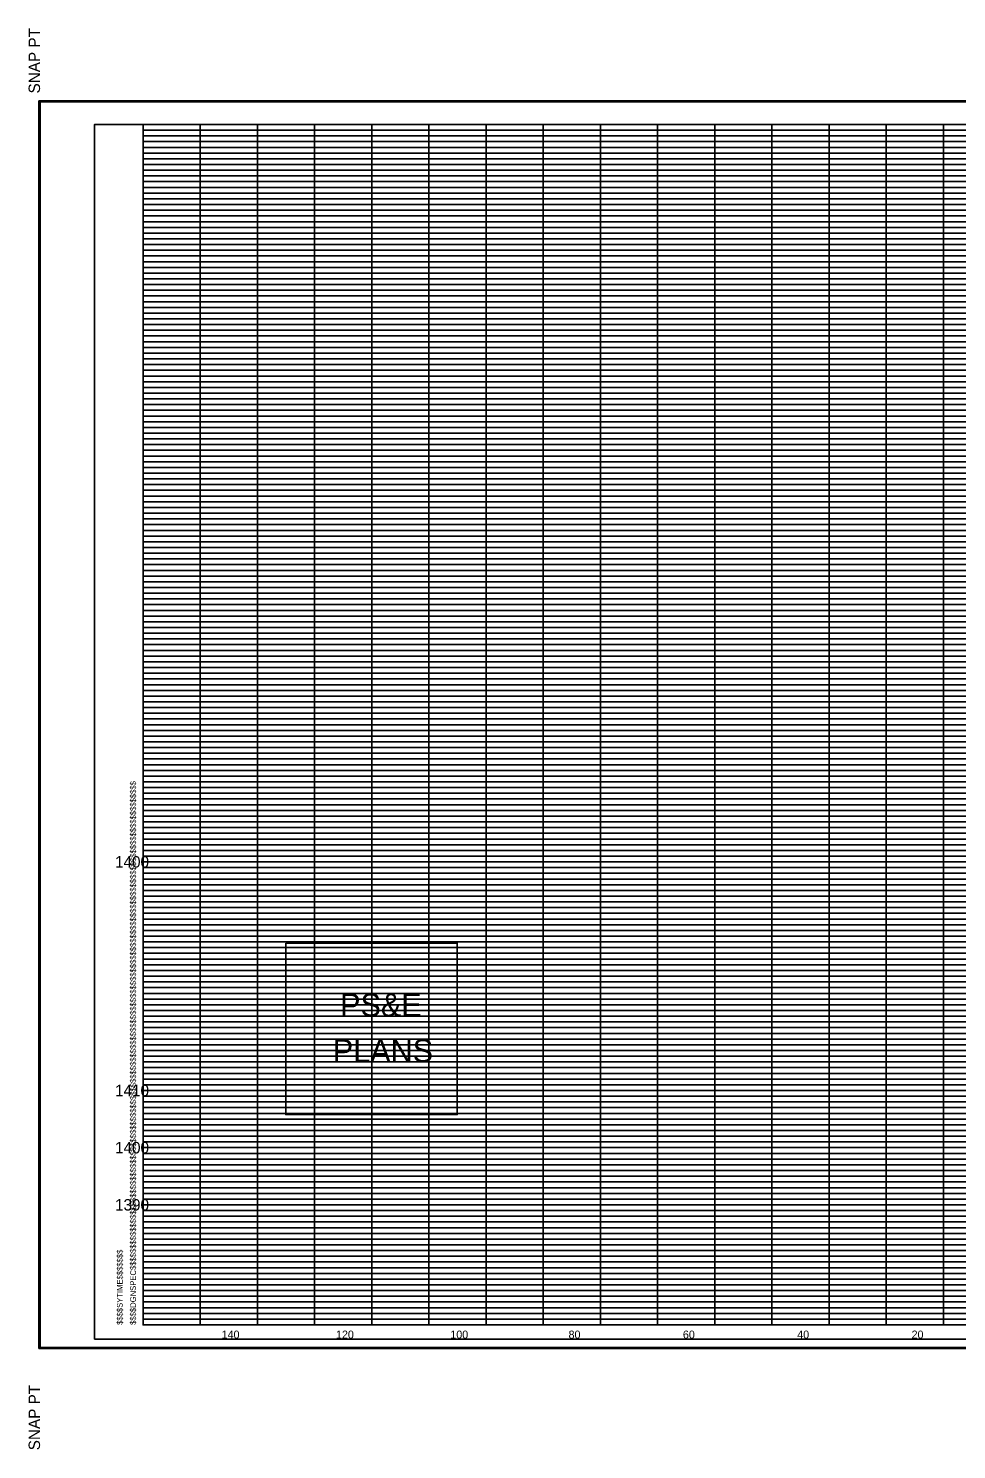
# Model space of a CAD drawing. Extents: x 980 to 1324, y 978 to 1497.
# Drawn here: x 979.9 to 1142.3, y 1248.2 to 1496.8 of the extents above; entities that cross this region are included whole.
import ezdxf

# ---------------------------------------------------------------- set-up
doc = ezdxf.new("R2010")
doc.units = 0
for name, color, linetype in [('DESIGN - SHEET - Corner Text', 7, 'Continuous'), ('DESIGN - SHEET - Light Grid', 7, 'Continuous'), ('DESIGN - SHEET - Linework', 7, 'Continuous'), ('DESIGN - SHEET - Plot Shape', 7, 'Continuous'), ('DESIGN - TYPICAL - Text', 7, 'Continuous')]:
    doc.layers.add(name, color=color, linetype=linetype)

# ---------------------------------------------------------------- blocks, each defined once
blk = doc.blocks.new('XSTSHT')
at = {"layer": 'DESIGN - SHEET - Light Grid'}
for p, q in [((0, 20.9), (8, 20.9)), ((8, 20.9), (16, 20.9)), ((0, 20.8), (8, 20.8)), ((0, 20.7), (8, 20.7)), ((8, 20.8), (16, 20.8)), ((8, 20.7), (16, 20.7)), ((0, 20.6), (8, 20.6)), ((0, 20.5), (8, 20.5)), ((0, 20.4), (8, 20.4)), ((8, 20.6), (16, 20.6)), ((8, 20.5), (16, 20.5)), ((8, 20.4), (16, 20.4)), ((0, 20.3), (8, 20.3)), ((0, 20.2), (8, 20.2)), ((8, 20.3), (16, 20.3)), ((8, 20.2), (16, 20.2)), ((0, 20.1), (8, 20.1)), ((0, 19.9), (8, 19.9)), ((8, 20.1), (16, 20.1)), ((8, 19.9), (16, 19.9)), ((0, 19.8), (8, 19.8)), ((0, 19.7), (8, 19.7)), ((8, 19.8), (16, 19.8)), ((8, 19.7), (16, 19.7)), ((0, 19.6), (8, 19.6)), ((0, 19.5), (8, 19.5)), ((0, 19.4), (8, 19.4)), ((8, 19.6), (16, 19.6)), ((8, 19.5), (16, 19.5)), ((8, 19.4), (16, 19.4)), ((0, 19.3), (8, 19.3)), ((0, 19.2), (8, 19.2)), ((8, 19.3), (16, 19.3)), ((8, 19.2), (16, 19.2)), ((0, 19.1), (8, 19.1)), ((0, 18.9), (8, 18.9)), ((8, 19.1), (16, 19.1)), ((8, 18.9), (16, 18.9)), ((0, 18.8), (8, 18.8)), ((0, 18.7), (8, 18.7)), ((8, 18.8), (16, 18.8)), ((8, 18.7), (16, 18.7)), ((0, 18.6), (8, 18.6)), ((0, 18.5), (8, 18.5)), ((0, 18.4), (8, 18.4)), ((8, 18.6), (16, 18.6)), ((8, 18.5), (16, 18.5)), ((8, 18.4), (16, 18.4)), ((0, 18.3), (8, 18.3)), ((0, 18.2), (8, 18.2)), ((8, 18.3), (16, 18.3)), ((8, 18.2), (16, 18.2)), ((0, 18.1), (8, 18.1)), ((8, 18.1), (16, 18.1)), ((0, 17.9), (8, 17.9)), ((0, 17.8), (8, 17.8)), ((0, 17.7), (8, 17.7)), ((8, 17.9), (16, 17.9)), ((8, 17.8), (16, 17.8)), ((8, 17.7), (16, 17.7)), ((0, 17.6), (8, 17.6)), ((0, 17.5), (8, 17.5)), ((8, 17.6), (16, 17.6)), ((8, 17.5), (16, 17.5)), ((0, 17.4), (8, 17.4)), ((0, 17.3), (8, 17.3)), ((0, 17.2), (8, 17.2)), ((8, 17.4), (16, 17.4)), ((8, 17.3), (16, 17.3)), ((8, 17.2), (16, 17.2)), ((0, 17.1), (8, 17.1)), ((8, 17.1), (16, 17.1)), ((0, 16.9), (8, 16.9)), ((0, 16.8), (8, 16.8)), ((0, 16.7), (8, 16.7)), ((8, 16.9), (16, 16.9)), ((8, 16.8), (16, 16.8)), ((8, 16.7), (16, 16.7)), ((0, 16.6), (8, 16.6)), ((0, 16.5), (8, 16.5)), ((8, 16.6), (16, 16.6)), ((8, 16.5), (16, 16.5)), ((0, 16.4), (8, 16.4)), ((0, 16.3), (8, 16.3)), ((0, 16.2), (8, 16.2)), ((8, 16.4), (16, 16.4)), ((8, 16.3), (16, 16.3)), ((8, 16.2), (16, 16.2)), ((0, 16.1), (8, 16.1)), ((8, 16.1), (16, 16.1)), ((0, 15.9), (8, 15.9)), ((0, 15.8), (8, 15.8)), ((0, 15.7), (8, 15.7)), ((8, 15.9), (16, 15.9)), ((8, 15.8), (16, 15.8)), ((8, 15.7), (16, 15.7)), ((0, 15.6), (8, 15.6)), ((0, 15.5), (8, 15.5)), ((8, 15.6), (16, 15.6)), ((8, 15.5), (16, 15.5)), ((0, 15.4), (8, 15.4)), ((0, 15.3), (8, 15.3)), ((0, 15.2), (8, 15.2)), ((8, 15.4), (16, 15.4)), ((8, 15.3), (16, 15.3)), ((8, 15.2), (16, 15.2)), ((0, 15.1), (8, 15.1)), ((8, 15.1), (16, 15.1)), ((0, 14.9), (8, 14.9)), ((0, 14.8), (8, 14.8)), ((0, 14.7), (8, 14.7)), ((8, 14.9), (16, 14.9)), ((8, 14.8), (16, 14.8)), ((8, 14.7), (16, 14.7)), ((0, 14.6), (8, 14.6)), ((0, 14.5), (8, 14.5)), ((8, 14.6), (16, 14.6)), ((8, 14.5), (16, 14.5)), ((0, 14.4), (8, 14.4)), ((0, 14.3), (8, 14.3)), ((0, 14.2), (8, 14.2)), ((8, 14.4), (16, 14.4)), ((8, 14.3), (16, 14.3)), ((8, 14.2), (16, 14.2)), ((0, 14.1), (8, 14.1)), ((8, 14.1), (16, 14.1)), ((0, 13.9), (8, 13.9)), ((0, 13.8), (8, 13.8)), ((0, 13.7), (8, 13.7)), ((8, 13.9), (16, 13.9)), ((8, 13.8), (16, 13.8)), ((8, 13.7), (16, 13.7)), ((0, 13.6), (8, 13.6)), ((0, 13.5), (8, 13.5)), ((8, 13.6), (16, 13.6)), ((8, 13.5), (16, 13.5)), ((0, 13.4), (8, 13.4)), ((0, 13.3), (8, 13.3)), ((0, 13.2), (8, 13.2)), ((8, 13.4), (16, 13.4)), ((8, 13.3), (16, 13.3)), ((8, 13.2), (16, 13.2)), ((0, 13.1), (8, 13.1)), ((8, 13.1), (16, 13.1)), ((0, 12.9), (8, 12.9)), ((0, 12.8), (8, 12.8)), ((0, 12.7), (8, 12.7)), ((8, 12.9), (16, 12.9)), ((8, 12.8), (16, 12.8)), ((8, 12.7), (16, 12.7)), ((0, 12.6), (8, 12.6)), ((0, 12.5), (8, 12.5)), ((8, 12.6), (16, 12.6)), ((8, 12.5), (16, 12.5)), ((0, 12.4), (8, 12.4)), ((0, 12.3), (8, 12.3)), ((0, 12.2), (8, 12.2)), ((8, 12.4), (16, 12.4)), ((8, 12.3), (16, 12.3)), ((8, 12.2), (16, 12.2)), ((0, 12.1), (8, 12.1)), ((8, 12.1), (16, 12.1)), ((0, 11.9), (8, 11.9)), ((0, 11.8), (8, 11.8)), ((0, 11.7), (8, 11.7)), ((8, 11.9), (16, 11.9)), ((8, 11.8), (16, 11.8)), ((8, 11.7), (16, 11.7)), ((0, 11.6), (8, 11.6)), ((0, 11.5), (8, 11.5)), ((8, 11.6), (16, 11.6)), ((8, 11.5), (16, 11.5)), ((0, 11.4), (8, 11.4)), ((0, 11.3), (8, 11.3)), ((0, 11.2), (8, 11.2)), ((8, 11.4), (16, 11.4)), ((8, 11.3), (16, 11.3)), ((8, 11.2), (16, 11.2)), ((0, 11.1), (8, 11.1)), ((8, 11.1), (16, 11.1)), ((0, 10.9), (8, 10.9)), ((0, 10.8), (8, 10.8)), ((0, 10.7), (8, 10.7)), ((8, 10.9), (16, 10.9)), ((8, 10.8), (16, 10.8)), ((8, 10.7), (16, 10.7)), ((0, 10.6), (8, 10.6)), ((0, 10.5), (8, 10.5)), ((8, 10.6), (16, 10.6)), ((8, 10.5), (16, 10.5)), ((0, 10.4), (8, 10.4)), ((0, 10.3), (8, 10.3)), ((0, 10.2), (8, 10.2)), ((8, 10.4), (16, 10.4)), ((8, 10.3), (16, 10.3)), ((8, 10.2), (16, 10.2)), ((0, 10.1), (8, 10.1)), ((8, 10.1), (16, 10.1)), ((0, 9.9), (8, 9.9)), ((0, 9.8), (8, 9.8)), ((0, 9.7), (8, 9.7)), ((8, 9.9), (16, 9.9)), ((8, 9.8), (16, 9.8)), ((8, 9.7), (16, 9.7)), ((0, 9.6), (8, 9.6)), ((0, 9.5), (8, 9.5)), ((8, 9.6), (16, 9.6)), ((8, 9.5), (16, 9.5)), ((0, 9.4), (8, 9.4)), ((0, 9.3), (8, 9.3)), ((0, 9.2), (8, 9.2)), ((8, 9.4), (16, 9.4)), ((8, 9.3), (16, 9.3)), ((8, 9.2), (16, 9.2)), ((0, 9.1), (8, 9.1)), ((8, 9.1), (16, 9.1)), ((0, 8.9), (8, 8.9)), ((0, 8.8), (8, 8.8)), ((8, 8.9), (16, 8.9)), ((8, 8.8), (16, 8.8)), ((0, 8.7), (8, 8.7)), ((0, 8.6), (8, 8.6)), ((0, 8.5), (8, 8.5)), ((8, 8.7), (16, 8.7)), ((8, 8.6), (16, 8.6)), ((8, 8.5), (16, 8.5)), ((0, 8.4), (8, 8.4)), ((0, 8.3), (8, 8.3)), ((8, 8.4), (16, 8.4)), ((8, 8.3), (16, 8.3)), ((0, 8.2), (8, 8.2)), ((0, 8.1), (8, 8.1)), ((8, 8.2), (16, 8.2)), ((8, 8.1), (16, 8.1)), ((0, 7.9), (8, 7.9)), ((0, 7.8), (8, 7.8)), ((8, 7.9), (16, 7.9)), ((8, 7.8), (16, 7.8)), ((0, 7.7), (8, 7.7)), ((0, 7.6), (8, 7.6)), ((0, 7.5), (8, 7.5)), ((8, 7.7), (16, 7.7)), ((8, 7.6), (16, 7.6)), ((8, 7.5), (16, 7.5)), ((0, 7.4), (8, 7.4)), ((0, 7.3), (8, 7.3)), ((8, 7.4), (16, 7.4)), ((8, 7.3), (16, 7.3)), ((0, 7.2), (8, 7.2)), ((0, 7.1), (8, 7.1)), ((8, 7.2), (16, 7.2)), ((8, 7.1), (16, 7.1)), ((0, 6.9), (8, 6.9)), ((0, 6.8), (8, 6.8)), ((8, 6.9), (16, 6.9)), ((8, 6.8), (16, 6.8)), ((0, 6.7), (8, 6.7)), ((0, 6.6), (8, 6.6)), ((0, 6.5), (8, 6.5)), ((8, 6.7), (16, 6.7)), ((8, 6.6), (16, 6.6)), ((8, 6.5), (16, 6.5)), ((0, 6.4), (8, 6.4)), ((0, 6.3), (8, 6.3)), ((8, 6.4), (16, 6.4)), ((8, 6.3), (16, 6.3)), ((0, 6.2), (8, 6.2)), ((0, 6.1), (8, 6.1)), ((8, 6.2), (16, 6.2)), ((8, 6.1), (16, 6.1)), ((0, 5.9), (8, 5.9)), ((0, 5.8), (8, 5.8)), ((8, 5.9), (16, 5.9)), ((8, 5.8), (16, 5.8)), ((0, 5.7), (8, 5.7)), ((0, 5.6), (8, 5.6)), ((0, 5.5), (8, 5.5)), ((8, 5.7), (16, 5.7)), ((8, 5.6), (16, 5.6)), ((8, 5.5), (16, 5.5)), ((0, 5.4), (8, 5.4)), ((0, 5.3), (8, 5.3)), ((8, 5.4), (16, 5.4)), ((8, 5.3), (16, 5.3)), ((0, 5.2), (8, 5.2)), ((0, 5.1), (8, 5.1)), ((8, 5.2), (16, 5.2)), ((8, 5.1), (16, 5.1)), ((0, 4.9), (8, 4.9)), ((0, 4.8), (8, 4.8)), ((8, 4.9), (16, 4.9)), ((8, 4.8), (16, 4.8)), ((0, 4.7), (8, 4.7)), ((0, 4.6), (8, 4.6)), ((0, 4.5), (8, 4.5)), ((8, 4.7), (16, 4.7)), ((8, 4.6), (16, 4.6)), ((8, 4.5), (16, 4.5)), ((0, 4.4), (8, 4.4)), ((0, 4.3), (8, 4.3)), ((8, 4.4), (16, 4.4)), ((8, 4.3), (16, 4.3)), ((0, 4.2), (8, 4.2)), ((0, 4.1), (8, 4.1)), ((8, 4.2), (16, 4.2)), ((8, 4.1), (16, 4.1)), ((0, 3.9), (8, 3.9)), ((0, 3.8), (8, 3.8)), ((8, 3.9), (16, 3.9)), ((8, 3.8), (16, 3.8)), ((0, 3.7), (8, 3.7)), ((0, 3.6), (8, 3.6)), ((0, 3.5), (8, 3.5)), ((8, 3.7), (16, 3.7)), ((8, 3.6), (16, 3.6)), ((8, 3.5), (16, 3.5)), ((0, 3.4), (8, 3.4)), ((0, 3.3), (8, 3.3)), ((8, 3.4), (16, 3.4)), ((8, 3.3), (16, 3.3)), ((0, 3.2), (8, 3.2)), ((0, 3.1), (8, 3.1)), ((8, 3.2), (16, 3.2)), ((8, 3.1), (16, 3.1)), ((0, 2.9), (8, 2.9)), ((0, 2.8), (8, 2.8)), ((8, 2.9), (16, 2.9)), ((8, 2.8), (16, 2.8)), ((0, 2.7), (8, 2.7)), ((0, 2.6), (8, 2.6)), ((0, 2.5), (8, 2.5)), ((8, 2.7), (16, 2.7)), ((8, 2.6), (16, 2.6)), ((8, 2.5), (16, 2.5)), ((0, 2.4), (8, 2.4)), ((0, 2.3), (8, 2.3)), ((8, 2.4), (16, 2.4)), ((8, 2.3), (16, 2.3)), ((0, 2.2), (8, 2.2)), ((0, 2.1), (8, 2.1)), ((8, 2.2), (16, 2.2)), ((8, 2.1), (16, 2.1)), ((0, 1.9), (8, 1.9)), ((0, 1.8), (8, 1.8)), ((8, 1.9), (16, 1.9)), ((8, 1.8), (16, 1.8)), ((0, 1.7), (8, 1.7)), ((0, 1.6), (8, 1.6)), ((0, 1.5), (8, 1.5)), ((8, 1.7), (16, 1.7)), ((8, 1.6), (16, 1.6)), ((8, 1.5), (16, 1.5)), ((0, 1.4), (8, 1.4)), ((0, 1.3), (8, 1.3)), ((8, 1.4), (16, 1.4)), ((8, 1.3), (16, 1.3)), ((0, 1.2), (8, 1.2)), ((0, 1.1), (8, 1.1)), ((8, 1.2), (16, 1.2)), ((8, 1.1), (16, 1.1)), ((0, 0.9), (8, 0.9)), ((0, 0.8), (8, 0.8)), ((8, 0.9), (16, 0.9)), ((8, 0.8), (16, 0.8)), ((0, 0.7), (8, 0.7)), ((0, 0.6), (8, 0.6)), ((0, 0.5), (8, 0.5)), ((8, 0.7), (16, 0.7)), ((8, 0.6), (16, 0.6)), ((8, 0.5), (16, 0.5)), ((0, 0.4), (8, 0.4)), ((0, 0.3), (8, 0.3)), ((8, 0.4), (16, 0.4)), ((8, 0.3), (16, 0.3)), ((0, 0.2), (8, 0.2)), ((0, 0.1), (8, 0.1)), ((8, 0.2), (16, 0.2)), ((8, 0.1), (16, 0.1))]:
    blk.add_line(p, q, dxfattribs=at)
at = {"layer": 'DESIGN - SHEET - Linework'}
for p, q in [((-1.823, -0.414), (-1.823, 21.414)), ((-1.823, 21.414), (32.217, 21.414)), ((1, 0), (1, 21)), ((2, 0), (2, 21)), ((3, 0), (3, 21)), ((4, 0), (4, 21)), ((5, 0), (5, 21)), ((6, 0), (6, 21)), ((7, 0), (7, 21)), ((8, 0), (8, 21)), ((9, 0), (9, 21)), ((10, 0), (10, 21)), ((11, 0), (11, 21)), ((12, 0), (12, 21)), ((13, 0), (13, 21)), ((14, 0), (14, 21)), ((0, 20), (28, 20)), ((0, 19), (32, 19)), ((0, 18), (32, 18)), ((0, 17), (32, 17)), ((0, 16), (32, 16)), ((0, 15), (32, 15)), ((0, 14), (32, 14)), ((0, 13), (32, 13)), ((0, 12), (32, 12)), ((0, 11), (32, 11)), ((0, 10), (32, 10)), ((0, 9), (32, 9)), ((0, 8), (32, 8)), ((0, 7), (32, 7)), ((0, 6), (32, 6)), ((0, 5), (32, 5)), ((0, 4), (32, 4)), ((0, 3), (32, 3)), ((0, 2), (32, 2)), ((0, 1), (32, 1)), ((-1.823, -0.414), (32.217, -0.414))]:
    blk.add_line(p, q, dxfattribs=at)
blk.add_lwpolyline([(0, 21), (0, 0), (32, 0), (32, 21), (0, 21)], dxfattribs=at)
at = {"layer": 'DESIGN - SHEET - Plot Shape'}
for points in [[(-1.803, 21.394), (32.197, 21.394), (32.197, -0.394), (-1.803, -0.394)], [(-0.85, 21), (32, 21), (32, -0.25), (-0.85, -0.25)]]:
    blk.add_lwpolyline(points, close=True, dxfattribs=at)
at = {"layer": 'DESIGN - SHEET - Corner Text'}
for s, height, p in [('  SNAP PT', 0.2, (-1.803, 21.394)), ('$$$$DGNSPEC$$$$$$$$$$$$$$$$$$$$$$$$$$$$$$$$$$$$$$$$$$$$$$$$$$$$$$$$$$$$$$$$$$$$$$$$$$$$$$$$$$$$$$$$$$$$$$$$$$$$$$$$$$$$$$$$$$$', 0.100002, (-0.126, 0)), ('$$$$SYTIME$$$$$$$', 0.1, (-0.358, 0)), ('SNAP PT  ', 0.2, (-1.803, -2.194))]:
    blk.add_text(s, height=height, rotation=90, dxfattribs=at).set_placement(p)

msp = doc.modelspace()

# ---------------------------------------------------------------- linework, layer by layer
at = {"layer": 'DESIGN - SHEET - Corner Text'}
msp.add_lwpolyline([(1024.94, 1336.8), (1024.94, 1306.8), (1054.94, 1306.8), (1054.94, 1336.8)], close=True, dxfattribs=at)
at = {"layer": 'DESIGN - SHEET - Plot Shape'}
msp.add_lwpolyline([(991.5, 1267.5), (1320, 1267.5), (1320, 1480), (991.5, 1480)], close=True, dxfattribs=at)

# ---------------------------------------------------------------- block references
at = {"layer": 'DESIGN - TYPICAL - Text', "xscale": 10, "yscale": 10}
msp.add_blockref('XSTSHT', (1000, 1270), dxfattribs=at)

# ---------------------------------------------------------------- texts
at = {"layer": 'DESIGN - SHEET - Corner Text'}
for s, p in [('PS&E', (1034.46, 1323.97)), ('PLANS', (1033.18, 1315.97))]:
    msp.add_text(s, height=4, dxfattribs=at).set_placement(p)
at = {"layer": 'DESIGN - TYPICAL - Text'}
for s, height, p in [('     1400     ', 2, (991.37, 1350)), ('     1410     ', 2, (991.37, 1310)), ('     1400     ', 2, (991.37, 1300)), ('     1390     ', 2, (991.37, 1290)), ('     140     ', 1.4, (1011.14, 1267.6)), ('     120     ', 1.4, (1031.14, 1267.6)), ('     100     ', 1.4, (1051.14, 1267.6)), ('     80     ', 1.4, (1071.82, 1267.6)), ('     60     ', 1.4, (1091.82, 1267.6)), ('     40     ', 1.4, (1111.82, 1267.6)), ('     20     ', 1.4, (1131.82, 1267.6))]:
    msp.add_text(s, height=height, dxfattribs=at).set_placement(p)

doc.saveas('drawing.dxf')
